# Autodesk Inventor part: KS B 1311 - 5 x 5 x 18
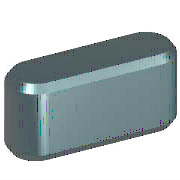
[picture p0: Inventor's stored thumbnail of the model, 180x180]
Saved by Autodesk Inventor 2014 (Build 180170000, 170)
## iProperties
IsCustomPart: 0
Created: 2009-02
Part Number: KS B 1311 - 5 x 5 x 18
Material: 강, 연강
Description: 키 및 해당 키홈
Document SubType Name: Modeling
Standard: KS B 1311
Designer: KYOUNG IL JANG
Standards Organization: KS
Language: ko-KR
Size Designation: 5 x 5 x 18
Categories: <MemberInstance><Categories><Category DisplayName="샤프트 부품" InternalName="7f7aeb1f-a693-4053-b835-cee3144e0d98" Mnemonic="SHFT"><Category DisplayName="키" Interna
Density: 7.86 g/cm^3
Appearance: 강철
Mass: 3.27476 g
Surface Area: 3.57848 cm^2
Volume: 0.416636 cm^3
Author: KYOUNG IL JANG
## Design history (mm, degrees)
workplane "Work Plane1"
workplane "Work Plane2"
sketch "스케치1"
  geometry: L1 (2.5, 2.5)-(15.5, 2.5); L2 (15.5, -2.5)-(2.5, -2.5); L3 (0, 9.4)-(0, -7.4) reference; L4 (-5, 0)-(30, 0) reference; L5 (18, 0)-(18, 7); A1 r 2.5 centre (2.5, 0) between (2.5, 2.5) and (2.5, -2.5); A2 r 2.5 centre (15.5, 0) between (15.5, -2.5) and (15.5, 2.5)
  constraints: 6 end point, 5 point on circle, 4 tangent, 3 point on line, 2 centre point, 1 horizontal, 1 parallel, 1 perpendicular
  dimensions: "d0" = 2.5 radius of A1 (= 0.5 x PB); "d13" = 2.5 radius of A2 (= 0.5 x PB); "d14" = 18 distance between parallel lines of L5 L3 (= NLG)
extrude "본체1" new body sketch "스케치1" taper "d3" = 0 deg; stored distance "d4" = 10
workplane "Work Plane3"
body "Solid1"
chamfer "모따기1" distance "d8" = 0.4 (= PHH); stored, may be unused: second distance "d9" = 0.4 (= PHH), angle "d15" = 45 deg
other parameters: "d1" = -3 (= -PNT), "d2" = 2 (= PH - PNT), "NLG" = 18 [user parameter; used in 3 equation terms], "PB" = 5 [user parameter; used in 2 equation terms], "PNT" = 3 [user parameter; used in 2 equation terms], "PH" = 5 [user parameter; used in 1 equation term], "PHH" = 0.4 [user parameter; used in 2 equation terms], "d10" = 0, "d16" = 0, "d17" = 0, "d18" = 0, "WDMIN" = 12 [user parameter], "PLB2" = 18 (= NLG) [user parameter], "WDMAX" = 17 [user parameter], "PLB1" = 18 (= NLG) [user parameter], "RR" = 0.16 [user parameter], "PUEB" = 2.3 [user parameter]
